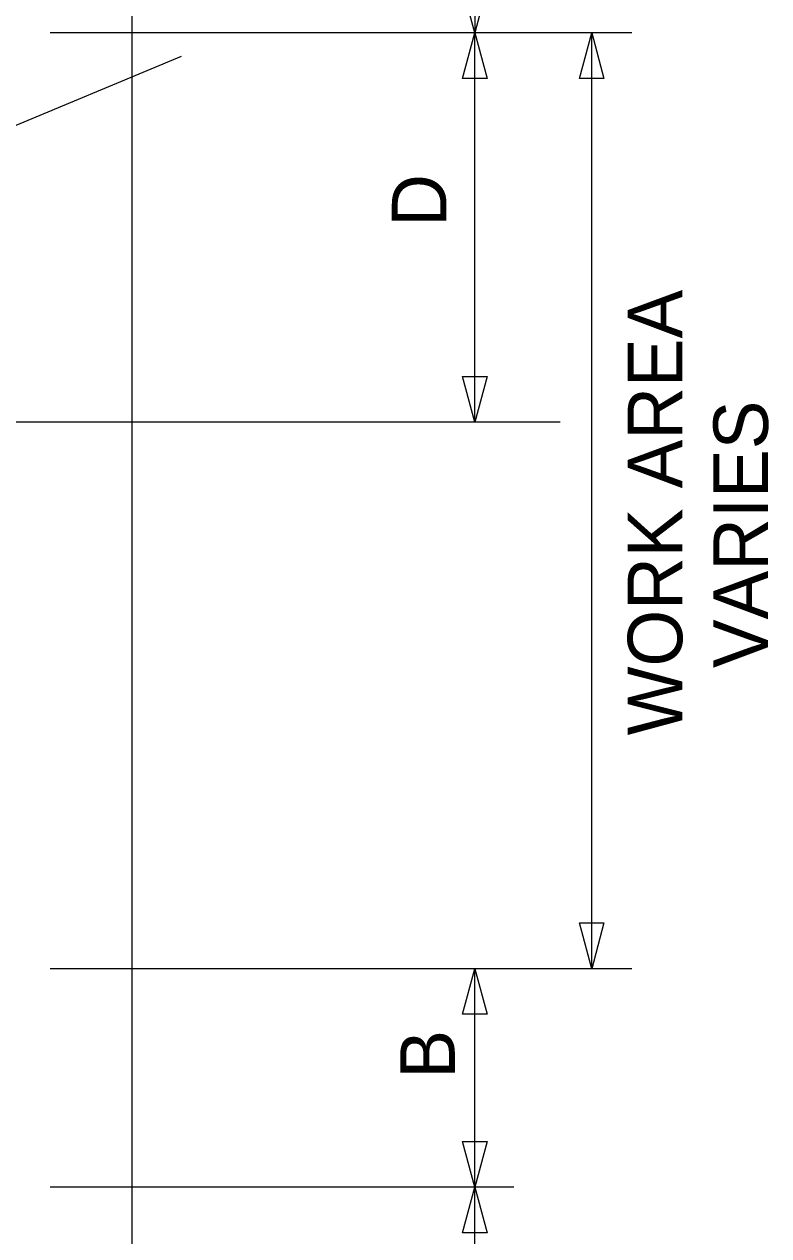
# Model space of a CAD drawing. Extents: x 16731 to 19504, y 5932 to 7446.
# Drawn here: x 17124.9 to 17220.4, y 6260.9 to 6416.5 of the extents above; entities that cross this region are included whole.
import ezdxf

# ---------------------------------------------------------------- set-up
doc = ezdxf.new("R2010")
doc.units = 0
doc.layers.add('PAVT_EDGE_EX', color=7, linetype='Continuous')
doc.layers.add('TYPICAL_TEXT_DIMEN_PR', color=7, linetype='Continuous')

msp = doc.modelspace()

# ---------------------------------------------------------------- linework, layer by layer
at = {"layer": 'PAVT_EDGE_EX'}
msp.add_line((17138.71, 6865.32), (17138.71, 6112.72), dxfattribs=at)
at = {"layer": 'TYPICAL_TEXT_DIMEN_PR'}
for p, q in [((17182.71, 6439.82), (17182.71, 6415.36)), ((17182.71, 6415.36), (17181.14, 6421.22)), ((17184.28, 6421.22), (17182.71, 6415.36)), ((17202.87, 6415.36), (17128.21, 6415.36)), ((17181.14, 6409.49), (17182.71, 6415.36)), ((17182.71, 6365.36), (17182.71, 6415.36)), ((17182.71, 6415.36), (17184.28, 6409.49)), ((17196.14, 6409.49), (17197.71, 6415.36)), ((17197.71, 6295.18), (17197.71, 6415.36)), ((17197.71, 6415.36), (17199.28, 6409.49)), ((17145.03, 6412.31), (17039.48, 6368.33)), ((17182.71, 6409.49), (17181.14, 6409.49)), ((17184.28, 6409.49), (17182.71, 6409.49)), ((17197.71, 6409.49), (17196.14, 6409.49)), ((17199.28, 6409.49), (17197.71, 6409.49)), ((17182.71, 6365.36), (17181.14, 6371.22)), ((17181.14, 6371.22), (17182.71, 6371.22)), ((17182.71, 6371.22), (17184.28, 6371.22)), ((17184.28, 6371.22), (17182.71, 6365.36)), ((17193.68, 6365.36), (17057.11, 6365.36)), ((17197.71, 6295.18), (17196.14, 6301.05)), ((17196.14, 6301.05), (17197.71, 6301.05)), ((17197.71, 6301.05), (17199.28, 6301.05)), ((17199.28, 6301.05), (17197.71, 6295.18)), ((17202.87, 6295.18), (17128.21, 6295.18)), ((17181.14, 6289.32), (17182.71, 6295.18)), ((17182.71, 6267.12), (17182.71, 6295.18)), ((17182.71, 6295.18), (17184.28, 6289.32)), ((17182.71, 6289.32), (17181.14, 6289.32)), ((17184.28, 6289.32), (17182.71, 6289.32)), ((17182.71, 6267.12), (17181.14, 6272.99)), ((17181.14, 6272.99), (17182.71, 6272.99)), ((17182.71, 6272.99), (17184.28, 6272.99)), ((17184.28, 6272.99), (17182.71, 6267.12)), ((17187.71, 6267.12), (17128.21, 6267.12)), ((17181.14, 6261.26), (17182.71, 6267.12)), ((17182.71, 6267.12), (17184.28, 6261.26)), ((17182.71, 6179.17), (17182.71, 6267.12)), ((17182.71, 6261.26), (17181.14, 6261.26)), ((17184.28, 6261.26), (17182.71, 6261.26))]:
    msp.add_line(p, q, dxfattribs=at)

# ---------------------------------------------------------------- texts
for s, p in [('D', (17179.06, 6390.46)), ('WORK AREA', (17209.34, 6325.15)), ('VARIES', (17220.34, 6333.79)), ('B', (17180.15, 6281.07))]:
    msp.add_text(s, height=7, rotation=90, dxfattribs=at).set_placement(p)

doc.saveas('drawing.dxf')
